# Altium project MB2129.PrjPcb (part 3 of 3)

## Sheet USB_User_UC2.1.SchDoc: USB User
size A4; Date: Not used; ApprovedBy: Not used; CheckedBy: Not used; Author: Not used; CompanyName: STMicroelectronics; DrawnBy: Not used; Engineer: Not used; Organization: Not used; Address1: Not used; Address2: Not used; Address3: Not used; Address4: Not used; DocumentNumber: 11; Revision: Not used; SheetNumber: 11; SheetTotal: 14
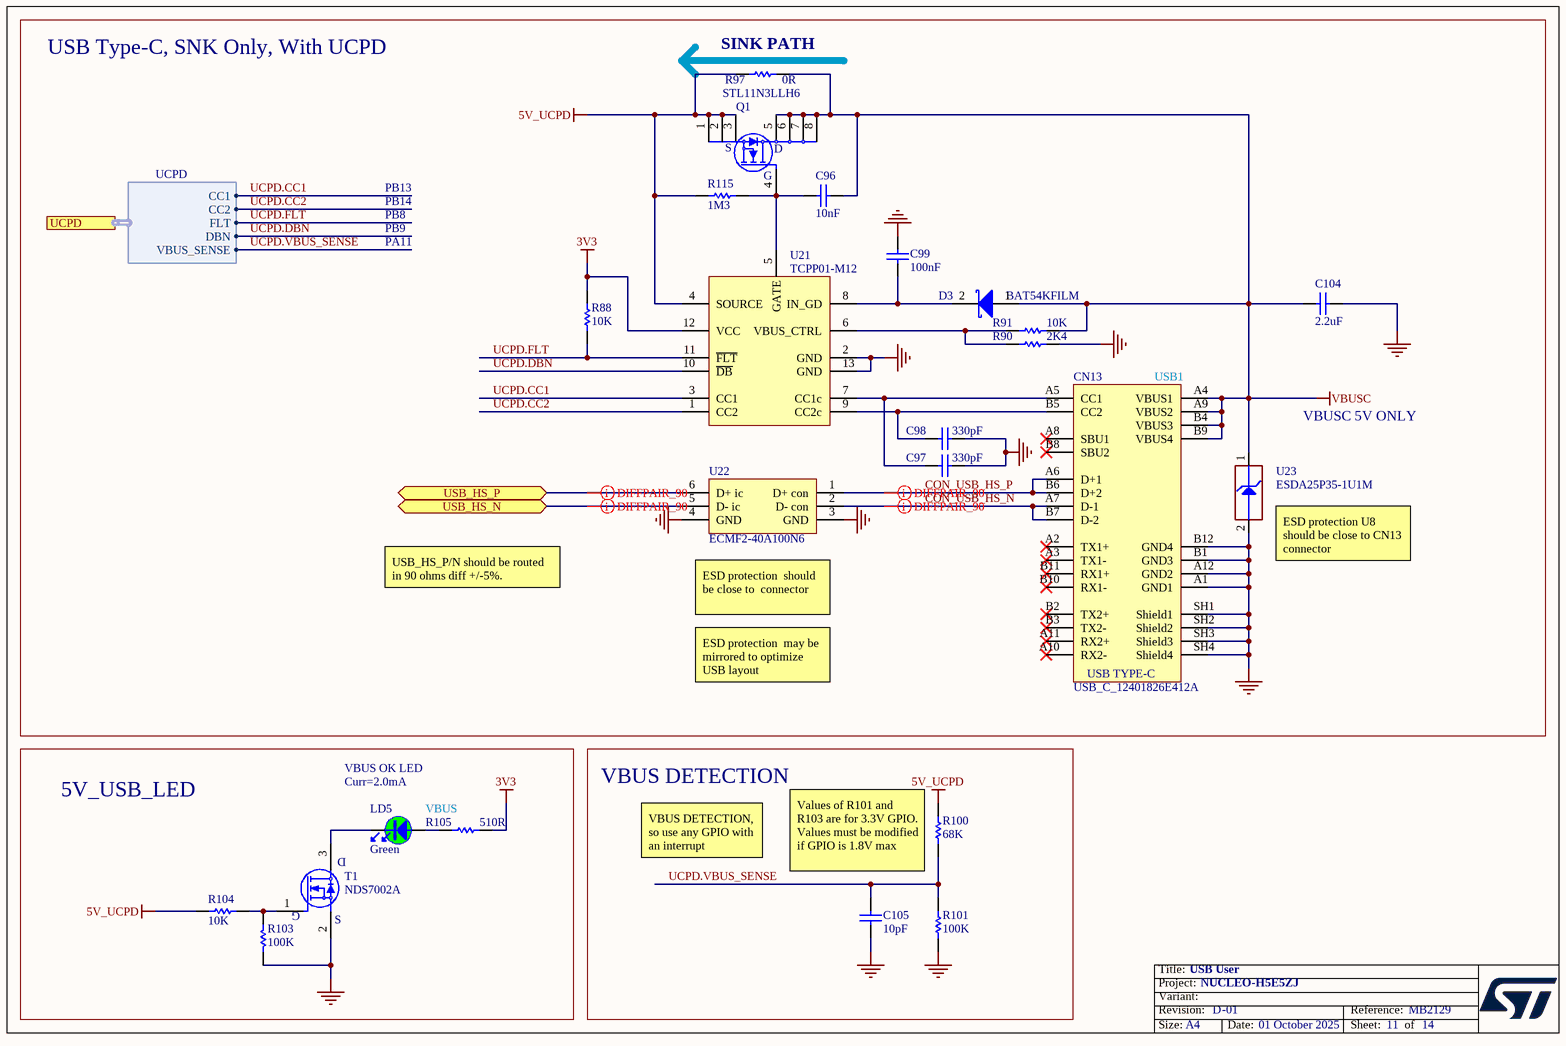
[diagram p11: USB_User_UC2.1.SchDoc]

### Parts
C96  value 10nF  [C0402]  (hidden comment: Capacitor)
C97  value 330pF  [C0402]  (hidden comment: Capacitor)
C98  value 330pF  [C0402]  (hidden comment: Capacitor)
C99  value 100nF  [C0603]  (hidden comment: Capacitor)
C104  value 2.2uF  [C0805]  (hidden comment: Capacitor)
C105  value 10pF  [C0402]  (hidden comment: Capacitor)
CN13  value USB_C_12401826E412A  [CON_USB-TYPEC_AMPHENOL_12401826E412A]  (hidden comment: USB_TYPE_C_Receptacle)
D3  value BAT54KFILM  [DIO_SOD523_1A_2K]  (hidden comment: SCHOTTKY_1A_2K)
LD5  value Green  [LED_0603_OSRAM_LG-Q396-PS-35_GREEN_1A2K_H0P4]  (hidden comment: LED_green)
Q1  STL11N3LLH6  [MOS_POWERFLAT_3P3X3P3_P065]
R88  value 10K  [R0402]  (hidden comment: Resistor)
R90  value 2K4  [R0402]  (hidden comment: Resistor)
R91  value 10K  [R0402]  (hidden comment: Resistor)
R97  value 0R  [R0402]  (hidden comment: Resistor)
R100  value 68K  [R0402]  (hidden comment: Resistor)
R101  value 100K  [R0402]  (hidden comment: Resistor)
R103  value 100K  [R0603]  (hidden comment: Resistor)
R104  value 10K  [R0603]  (hidden comment: Resistor)
R105  value 510R  [R0402]  (hidden comment: Resistor)
R115  value 1M3  [R0402]  (hidden comment: Resistor)
T1  value NDS7002A  [ICC_SOT23-3L_H1P12]  (hidden comment: MOSFET_N-CHANNEL)
U21  TCPP01-M12  [ICC_QFN12L-EPAD_3X3_P050]
U22  ECMF2-40A100N6  [ESD_UQFN-6L_1P45X1P4_P040]
U23  value ESDA25P35-1U1M  [ESD_QFN1610_2N_1K_2A]  (hidden comment: ESD-TRANSIL)

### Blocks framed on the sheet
USB Type-C, SNK Only, With UCPD: C96-C99 C104 CN13 D3 Q1 R88 R90 R91 R97 R115 U21-U23
5V_USB_LED: LD5 R103-R105 T1
VBUS DETECTION: C105 R100 R101

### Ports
UCPD (harness UCPD), USB_HS_N (bidir), USB_HS_P (bidir)

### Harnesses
UCPD: CC1, CC2, DBN, VBUS_SENSE, FLT

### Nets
3V3: R88.1 R105.2 U21.12(VCC)
5V_UCPD: Q1.1(S) Q1.2(S) Q1.3(S) R97.1 R100.2 R104.2 R115.1 U21.4(SOURCE)
GND: C97.2 C98.2 C99.2 C104.2 C105.1 CN13.A1(GND1) CN13.A12(GND2) CN13.B1(GND3) CN13.B12(GND4) CN13.SH1(Shield1) CN13.SH2(Shield2) CN13.SH3(Shield3) CN13.SH4(Shield4) R90.2 R101.1 R103.1 T1.2(S) U21.2(GND) U21.13(GND) U22.3(GND) U22.4(GND) U23.2(GND)
VBUSC: C96.2 C104.1 CN13.A4(VBUS1) CN13.A9(VBUS2) CN13.B4(VBUS3) CN13.B9(VBUS4) D3.1(A) Q1.5(D) Q1.6(D) Q1.7(D) Q1.8(D) R91.2 R97.2 U23.1(IO1)
CON_USB_HS_N: CN13.A7(D-1) CN13.B7(D-2) U22.2(D-_con)
CON_USB_HS_P: CN13.A6(D+1) CN13.B6(D+2) U22.1(D+_con)
UCPD.CC1: U21.3(CC1) ; port UCPD.CC1
UCPD.CC2: U21.1(CC2) ; port UCPD.CC2
UCPD.DBN: U21.10(~{DB}) ; port UCPD.DBN
UCPD.FLT: R88.2 U21.11(~{FLT}) ; port UCPD.FLT
UCPD.VBUS_SENSE: C105.2 R100.1 R101.2 ; port UCPD.VBUS_SENSE
USB_HS_N: U22.5(D-_ic) ; port USB_HS_N
USB_HS_P: U22.6(D+_ic) ; port USB_HS_P
NetC96_1: C96.1 Q1.4(G) R115.2 U21.5(GATE)
NetC97_1: C97.1 CN13.A5(CC1) U21.7(CC1c)
NetC98_1: C98.1 CN13.B5(CC2) U21.9(CC2c)
NetC99_1: C99.1 D3.2(K) U21.8(IN_GD)
NetLD5_1: LD5.1 R105.1
NetLD5_2: LD5.2 T1.3(D)
NetR90_1: R90.1 R91.1 U21.6(VBUS_CTRL)
NetR103_2: R103.2 R104.1 T1.1(G)

Not connected (* = marked no-connect by the designer): CN13 A2(TX1+)* A3(TX1-)* A8(SBU1)* A10(RX2-)* A11(RX2+)* B2(TX2+)* B3(TX2-)* B8(SBU2)* B10(RX1-)* B11(RX1+)*

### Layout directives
differential pair; differential pair class DiffPair_90; net class 90 ohms diff: CON_USB_HS_N, CON_USB_HS_P, USB_HS_N, USB_HS_P

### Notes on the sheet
- (near R97) SINK PATH
- PB13
- PB14
- PB8
- PB9
- PA11
- (near CN13) USB1
- VBUSC 5V ONLY
- USB_HS_P/N should be routed in 90 ohms diff +/-5%.
- (near U23) ESD protection U8 should be close to CN13 connector
- (near U22) ESD protection  should be close to  connector
- ESD protection  may be mirrored to optimize USB layout
- VBUS OK LED
- Curr=2.0mA
- (near LD5) VBUS
- VBUS DETECTION, so use any GPIO with an interrupt
- (near R100) Values of R101 and R103 are for 3.3V GPIO. Values must be modified if GPIO is 1.8V max

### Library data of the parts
C96 = MCD-02198: Capacitor, MLCC, 10nF, 50V, X7R, +/-10%, 0402, T=0.5mm; Part_Preference: Recommended; Manufacturer: YAGEO; Manufacturer_Part_Number: CC0402KRX7R9BB103; Order_Code_RS: 6169644; Component_Country_Of_Origin: China; ShowFields: YES; ID: 4298
C97 C98 = MCD-01579: Capacitor, MLCC, 330pF, 50V, NPO, +/-5%, 0402, T=0.5mm; Part_Preference: Recommended; Manufacturer: YAGEO; Manufacturer_Part_Number: CC0402JRNPO9BN331; Component_Country_Of_Origin: China; ShowFields: YES; ID: 3679
C99 = MCD-01099: Capacitor, MLCC, 100nF, 50V, X7R, +/-10%, 0603, T=0.8mm; Manufacturer_Part_Number: CC0603KRX7R9BB104; Manufacturer: YAGEO; BMS_Part_Number: 9142278; Part_Preference: Recommended; Order_Code_RS: 669-8767; Component_Country_Of_Origin: China; ShowFields: YES; ID: 3397
C104 = MCD-02372: Capacitor, MLCC, 2.2uF, 25V, X7R, +/-10%, 0805, T=1,25mm; Part_Preference: Recommended; Manufacturer: MURATA; Manufacturer_Part_Number: GRM21BR71E225KE11L
C105 = MCD-00015: Capacitor, MLCC, 10pF, 50V, NPO, +/-5%, 0402, T=0.5mm; Part_Preference: Recommended; Manufacturer: YAGEO; Manufacturer_Part_Number: CC0402JRNPO9BN100; Order_Code_RS: 3019160RL; Component_Country_Of_Origin: China; ShowFields: YES; ID: 2465
CN13 = MCD-03232: USB_TypeC, 24 pins, RA, SMD, T=2.96mm; Part_Type: Connector; Part_Preference: Recommended; Manufacturer: AMPHENOL ICC; Manufacturer_Part_Number: 12401826E412A; Component_Country_Of_Origin: China°; ShowFields: YES; ID: 5348
D3 = MCD-01677: Diode, Schottky, 0V9, 100mA, 40V, SOD523; Manufacturer: STMICROELECTRONICS; BMS_Part_Number: 9151123; Part_Preference: Recommended; Manufacturer_HQ_COO: EU; Order_Code_RS: 714-6869; Component_Country_Of_Origin: China; ShowFields: YES; ID: 3777
LD5 = MCD-02901: LED, Green, 2V, 20mA, 0603; Part_Type: Display; Part_Preference: Recommended; Manufacturer: EVERLIGHT; Manufacturer_Part_Number: 19-217/G7C-AN1P2/6T; Partial_Alternate_Internal_Part_Number: MCD-02400, MCD-00588; Component_Country_Of_Origin: China; ShowFields: YES; ID: 5017
Q1 = MCD-01810: Transistor, MOSFET, N-CH, 30V, 11A, PowerFLAT-8; Manufacturer: STMICROELECTRONICS; BMS_Part_Number: 9153561; Part_Preference: Recommended; Manufacturer_HQ_COO: EU; Partial_Alternate_Internal_Part_Number: MCD-03269, MCD-03325; Component_Country_Of_Origin: China; ShowFields: YES; ID: 3910
R88 R91 = MCD-00053: Resistor, 10K, 0402, +/-1%, 1/16W; BMS_Part_Number: 9131590; Part_Preference: Recommended; Manufacturer: YAGEO; Manufacturer_Part_Number: RC0402FR-0710KL; Order_Code_RS: 9239359; Component_Country_Of_Origin: China; ShowFields: YES; ID: 2539
R90 = MCD-00433: Resistor, 2K4, 0402, +/-1%, 1/16W; Part_Preference: Recommended; Manufacturer: YAGEO; Manufacturer_Part_Number: RC0402FR-072K4L; Component_Country_Of_Origin: China; ShowFields: YES; ID: 2843
R97 = MCD-00052: Resistor, 0R, 0402, +/-5%, 1/16W; Manufacturer_Part_Number: RC0402JR-070RL; Manufacturer: YAGEO; Part_Preference: Recommended; Order_Code_RS: 9232516RL; Component_Country_Of_Origin: China; ShowFields: YES; ID: 2540
R100 = MCD-00511: Resistor, 68K, 0402, +/-1%, 1/16W; Part_Preference: Recommended; Manufacturer: YAGEO; Manufacturer_Part_Number: RC0402FR-0768KL; Component_Country_Of_Origin: China; ShowFields: YES; ID: 3232
R101 = MCD-00059: Resistor, 100K, 0402, +/-1%, 1/16W; Part_Preference: Recommended; Manufacturer: YAGEO; Manufacturer_Part_Number: RC0402FR-07100KL; Partial_Alternate_Internal_Part_Number: MCD-03301; Order_Code_RS: 2421891; Component_Country_Of_Origin: China; ShowFields: YES; ID: 2533
R103 = MCD-00223: Resistor, 100K, 0603, +/- 1%, 1/10W; Manufacturer_Part_Number: RC0603FR-07100KL; Manufacturer: YAGEO; Part_Preference: Recommended; Component_Country_Of_Origin: China; ShowFields: YES; ID: 2647
R104 = MCD-00220: Resistor, 10K, 0603, +/-1%, 1/10W; Manufacturer_Part_Number: RC0603FR-0710KL; Manufacturer: YAGEO; Part_Preference: Recommended; Component_Country_Of_Origin: China; ShowFields: YES; ID: 2649
R105 = MCD-00064: Resistor, 510R, 0402, +/-1%, 1/16W; Manufacturer_Part_Number: RC0402FR-07510RL; Manufacturer: YAGEO; Part_Preference: Recommended; Order_Code_RS: 1458804; Component_Country_Of_Origin: China; ShowFields: YES; ID: 2525
R115 = MCD-00387: Resistor, 1M3, 0402, +/-1%, 1/16W; Part_Preference: Recommended; Manufacturer: YAGEO; Manufacturer_Part_Number: RC0402FR-071M3L; Component_Country_Of_Origin: China; ShowFields: YES; ID: 2893
T1 = MCD-01518: Transistor, MOSFET, N-CH, 60V, 280mA, SOT23-3; Part_Preference: Recommended; Manufacturer: ON SEMICONDUCTOR; Order_Code_RS: 671-1093P; ShowFields: YES; ID: 3618; Component_Country_Of_Origin: China°°
U21 = MCD-01809: IC, USB Type-C Overvoltage protection for VBUS and CC lines; Manufacturer: STMICROELECTRONICS; BMS_Part_Number: 9151145; Part_Preference: Recommended; Manufacturer_HQ_COO: EU; Order_Code_RS: 192-4677; Component_Country_Of_Origin: Malaysia; ShowFields: YES; ID: 3909
U22 = MCD-03060: IC, ESD protection and Common Filter High Speed serial Interfaces, 10.7 GHz; Part_Preference: Recommended; Manufacturer: STMICROELECTRONICS; Component_Country_Of_Origin: China; ShowFields: YES; ID: 5176
U23 = MCD-01207: Diode, ESD TVS, 22V, 200nA, 25V8, QFN1610; Manufacturer: STMICROELECTRONICS; BMS_Part_Number: 9179045; Part_Preference: Recommended; Manufacturer_HQ_COO: EU; Order_Code_RS: 163-9774; Component_Country_Of_Origin: China; ShowFields: YES; ID: 3289

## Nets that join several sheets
3V3: Ethernet (9 pins), STLINK_V3EC (LNK1.1), External_Debug_Interface (CN4.1), Connectors (5 pins), MCU_Power (JP5.1 R99.1), Power_Sources (C37.2 TP41.1 U15.1 U15.2), Peripherals (7 pins), M2_SerMem_Connector (CN19.64 SB40.2), USB_User_UC2.1 (R88.1 R105.2 U21.12)
5V: STLINK_V3EC (D2.1 R23.2), Connectors (CN6.5 CN7.18 R59.2), Power_Sources (7 pins)
5V_EXT: Connectors (CN7.6), Power_Sources (JP1.5)
5V_STLK: STLINK_V3EC (8 pins), Connectors (CN10.8), Power_Sources (JP1.1)
5V_UCPD: Power_Sources (JP1.7), USB_User_UC2.1 (8 pins)
AGND: Connectors (CN10.32), MCU_Power (6 pins)
GND: Ethernet (22 pins), STLINK_V3EC (109 pins), External_Debug_Interface (17 pins), Connectors (14 pins), MCU_Power (33 pins), MCU_IOs (7 pins), Power_Sources (17 pins), Peripherals (11 pins), M2_SerMem_Connector (23 pins), USB_User_UC2.1 (22 pins)
VBAT: Connectors (CN7.33), MCU_Power (C68.2 R65.2 U1.6)
VIN: Connectors (CN6.8 CN7.24 TP45.1), Power_Sources (R61.1)
VREFP: Connectors (SB10.1), MCU_Power (C69.2 C76.2 SB45.1 U1.32)
BOOT0: Connectors (CN7.7), MCU_IOs (U1.138), Peripherals (5 pins)
DBGIN.JTDI: STLINK_V3EC (R44.2), External_Debug_Interface (CN4.8 U5.1), Connectors (CN7.17), MCU_IOs (U1.110)
DBGIN.MCO: STLINK_V3EC (C3.2 R7.2 TP2.1), MCU_IOs (SB5.2)
DBGIN.SWCLK: STLINK_V3EC (R15.2), External_Debug_Interface (CN4.4 U20.1), Connectors (CN7.15), MCU_IOs (U1.109)
DBGIN.SWDIO: STLINK_V3EC (R45.2), External_Debug_Interface (CN4.2 U24.1), Connectors (CN7.13), MCU_IOs (U1.105)
DBGIN.SWO: STLINK_V3EC (R22.2), External_Debug_Interface (CN4.6 U10.1), Connectors (CN7.11), MCU_IOs (U1.133)
DBGIN.VCP_RX: STLINK_V3EC (R20.2 TP17.1), MCU_IOs (U1.78)
DBGIN.VCP_TX: STLINK_V3EC (R16.2 TP15.1), MCU_IOs (U1.77)
LED1: MCU_IOs (U1.37), Peripherals (SB8.1)
LED2: MCU_IOs (U1.10), Peripherals (LD2.2)
LED3: MCU_IOs (U1.4), Peripherals (LD3.2)
MEM_GPIO: Connectors (CN12.15), M2_SerMem_Connector (CN19.40)
MEM_LED1: Connectors (CN12.11), M2_SerMem_Connector (CN19.42)
MEM_LED2: Connectors (CN12.13), M2_SerMem_Connector (CN19.38)
NRST: Ethernet (SB35.1), STLINK_V3EC (R27.2 TP25.1), External_Debug_Interface (CN4.10 U6.1), Connectors (CN6.3 CN7.14), Peripherals (SB46.2), M2_SerMem_Connector (SB25.2)
PA0: Connectors (CN7.23), MCU_IOs (U1.34)
PA4: Connectors (CN7.32 CN8.3), MCU_IOs (U1.40)
PA6: Connectors (CN7.28 CN8.1), MCU_IOs (U1.42)
PA7: Connectors (CN7.30 CN8.2), MCU_IOs (U1.43)
PA8: Connectors (CN9.1 CN10.37), MCU_IOs (U1.100)
PA9: Connectors (CN5.1 CN10.21), MCU_IOs (U1.101)
PA10: Connectors (CN9.3 CN10.33), MCU_IOs (U1.102)
PA12: Connectors (SB6.1), MCU_IOs (U1.104)
PB0: Connectors (CN7.34 CN8.4), MCU_IOs (U1.46)
PB1: Connectors (CN10.18), MCU_IOs (U1.47)
PB4: Connectors (CN9.2 CN10.35), MCU_IOs (U1.134)
PB6: Connectors (SB30.1), MCU_IOs (U1.136), M2_SerMem_Connector (CN19.60)
PB7: Connectors (SB29.1), MCU_IOs (U1.137), M2_SerMem_Connector (CN19.58)
PB15: Connectors (CN10.26), MCU_IOs (U1.76)
PC2: Connectors (CN7.35), MCU_IOs (U1.28)
PC3: Connectors (CN7.37), MCU_IOs (U1.29)
PC9: Connectors (CN10.1), MCU_IOs (U1.99)
PC10: Connectors (CN7.1), MCU_IOs (U1.111)
PC11: Connectors (CN7.2), MCU_IOs (U1.112)
PC12: Connectors (CN7.3), MCU_IOs (U1.113)
PC14: Connectors (CN7.25), MCU_IOs (SB1.2)
PC15: Connectors (CN7.27), MCU_IOs (SB2.2)
PD3: Connectors (CN9.5 CN10.29), MCU_IOs (U1.117)
PD4: Ethernet (SB14.1), MCU_IOs (U1.118)
PD7: Connectors (SB32.1), MCU_IOs (U1.123), M2_SerMem_Connector (CN19.17)
PD10: Connectors (CN12.14), MCU_IOs (U1.79)
PD14: Connectors (CN10.4), MCU_IOs (U1.85)
PD15: Connectors (CN10.6), MCU_IOs (U1.86)
PE0: Connectors (CN10.10), MCU_IOs (U1.141)
PE4: Connectors (CN12.16), MCU_IOs (U1.3)
PE8: Connectors (CN10.30 SB6.2), MCU_IOs (U1.59)
PE9: Connectors (CN9.8 CN10.23), MCU_IOs (U1.60)
PE10: Connectors (CN10.28), MCU_IOs (U1.63)
PE11: Connectors (CN5.3 CN10.17), MCU_IOs (U1.64)
PE12: Connectors (CN5.6 CN10.11), MCU_IOs (U1.65), Peripherals (SB9.1)
PE13: Connectors (CN5.5 CN10.13), MCU_IOs (U1.66)
PE14: Connectors (CN5.4 CN10.15), MCU_IOs (U1.67)
PE15: Connectors (CN10.16), MCU_IOs (U1.68)
PF1: Connectors (CN9.4 CN10.31), MCU_IOs (U1.11)
PF2: Connectors (CN10.22), MCU_IOs (U1.12)
PF3: Connectors (CN9.7 CN10.25), MCU_IOs (U1.13)
PF4: Connectors (CN5.2 CN10.19), MCU_IOs (U1.14)
PF5: Connectors (CN5.10 CN10.3), MCU_IOs (U1.15)
PF6: Connectors (CN10.2), MCU_IOs (U1.18)
PF8: Connectors (CN10.36), MCU_IOs (U1.20)
PF9: Connectors (CN10.38), MCU_IOs (U1.21)
PF11: Connectors (CN7.38 CN8.6), MCU_IOs (U1.49)
PF12: Connectors (CN7.36 CN8.5), MCU_IOs (U1.50)
PF13: Connectors (CN10.34), MCU_IOs (U1.53)
PF14: Connectors (CN10.24), MCU_IOs (U1.54)
PF15: Connectors (CN7.4), MCU_IOs (U1.55)
PG0: Connectors (CN7.9), MCU_IOs (U1.56)
PG1: Connectors (CN7.10), MCU_IOs (U1.57)
PG2: Connectors (CN7.21), MCU_IOs (U1.87)
PG3: Connectors (CN12.12), MCU_IOs (U1.88)
PG4: Ethernet (SB38.2), Connectors (CN7.26), MCU_IOs (U1.89)
PG5: Connectors (SB36.1), MCU_IOs (U1.90), M2_SerMem_Connector (CN19.18)
PG6: Connectors (CN5.9 CN10.5), MCU_IOs (U1.91)
PG7: Ethernet (CN14.12 SB13.2 TP67.1), Connectors (CN12.18), MCU_IOs (U1.92)
PG9: Connectors (SB33.1), MCU_IOs (U1.124), M2_SerMem_Connector (CN19.19)
PG10: Connectors (SB31.1), MCU_IOs (U1.125), M2_SerMem_Connector (CN19.21)
PG11: Connectors (SB34.1), MCU_IOs (U1.126), M2_SerMem_Connector (CN19.16)
PG13: Connectors (SB37.1), MCU_IOs (U1.128), M2_SerMem_Connector (CN19.62)
PG15: Connectors (CN9.6 CN10.27), MCU_IOs (U1.132)
PH0: Connectors (CN7.29), MCU_IOs (SB3.2)
PH1: Connectors (CN7.31), MCU_IOs (SB4.2)
RESET_MCU: MCU_IOs (U1.25), Peripherals (5 pins)
RMII.CRS_DV: Ethernet (R71.1), MCU_IOs (U1.115)
RMII.MDC: Ethernet (U17.13), MCU_IOs (U1.27)
RMII.MDIO: Ethernet (R69.1 U17.12), MCU_IOs (U1.36)
RMII.REF_CLK: Ethernet (R77.1), MCU_IOs (U1.35)
RMII.RXD0: Ethernet (R74.1), MCU_IOs (U1.44)
RMII.RXD1: Ethernet (R75.1), MCU_IOs (U1.45)
RMII.TX_EN: Ethernet (R80.1), MCU_IOs (U1.41)
RMII.TXD0: Ethernet (R82.1), MCU_IOs (U1.73)
RMII.TXD1: Ethernet (R83.1), MCU_IOs (U1.127)
TRACE.CLK: External_Debug_Interface (R26.2 U9.1), MCU_IOs (U1.1)
TRACE.D0: External_Debug_Interface (R29.2 U25.1), MCU_IOs (U1.2)
TRACE.D1: External_Debug_Interface (R43.2 U26.1), MCU_IOs (U1.129)
TRACE.D2: External_Debug_Interface (R46.2 U27.1), MCU_IOs (U1.116)
TRACE.D3: External_Debug_Interface (R47.2 U28.1), MCU_IOs (U1.5)
UCPD.CC1: MCU_IOs (U1.74), USB_User_UC2.1 (U21.3)
UCPD.CC2: MCU_IOs (U1.75), USB_User_UC2.1 (U21.1)
UCPD.DBN: MCU_IOs (U1.140), USB_User_UC2.1 (U21.10)
UCPD.FLT: MCU_IOs (U1.139), USB_User_UC2.1 (R88.2 U21.11)
UCPD.VBUS_SENSE: MCU_IOs (U1.103), USB_User_UC2.1 (C105.2 R100.1 R101.2)
USB_HS_N: MCU_IOs (U1.96), USB_User_UC2.1 (U22.5)
USB_HS_P: MCU_IOs (U1.97), USB_User_UC2.1 (U22.6)
USER: MCU_IOs (U1.7), Peripherals (B1.1 B1.2 R110.2 U13.1)
XSPI1.CLK: Connectors (SB26.1), MCU_IOs (U1.22), M2_SerMem_Connector (R108.1)
XSPI1.DQS0: Connectors (SB28.1), MCU_IOs (U1.48), M2_SerMem_Connector (R107.1)
XSPI1.IO0: Connectors (SB7.1), MCU_IOs (U1.80), M2_SerMem_Connector (R51.1)
XSPI1.IO1: Connectors (SB15.1), MCU_IOs (U1.81), M2_SerMem_Connector (R52.1)
XSPI1.IO2: Connectors (SB16.1), MCU_IOs (U1.19), M2_SerMem_Connector (R53.1)
XSPI1.IO3: Connectors (SB17.1), MCU_IOs (U1.82), M2_SerMem_Connector (R56.1)
XSPI1.IO4: Connectors (SB18.1), MCU_IOs (U1.58), M2_SerMem_Connector (R57.1)
XSPI1.IO5: Connectors (SB20.1), MCU_IOs (U1.119), M2_SerMem_Connector (R58.1)
XSPI1.IO6: Connectors (SB21.1), MCU_IOs (U1.122), M2_SerMem_Connector (R63.1)
XSPI1.IO7: Connectors (SB22.1), MCU_IOs (U1.26), M2_SerMem_Connector (R66.1)
XSPI1.NCLK: Connectors (SB27.1), MCU_IOs (U1.135), M2_SerMem_Connector (R109.1)
XSPI1.NCS1: Connectors (SB23.1), MCU_IOs (U1.69), M2_SerMem_Connector (R67.1)
XSPI1.NCS2: Connectors (SB24.1), MCU_IOs (U1.114), M2_SerMem_Connector (R106.1)

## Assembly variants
H5E5ZJ_S: not fitted C17 C20 C24 CN11 CN12 CN17 R25 R37 R38 R39 R40 R41 R50 R92 R93 R97 R98 SB1 SB2 SB3 SB4 SB5 SB6 SB9 SB10 SB11 SB12 SB14 SB38 SB43 SB44 U7
H5E5ZJ: not fitted C17 C20 C24 CN11 CN12 CN17 HW3 R25 R37 R38 R39 R40 R41 R50 R92 R93 R97 R98 R99 SB1 SB2 SB3 SB4 SB5 SB6 SB9 SB10 SB11 SB14 SB38 SB39 SB43 SB44 U7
